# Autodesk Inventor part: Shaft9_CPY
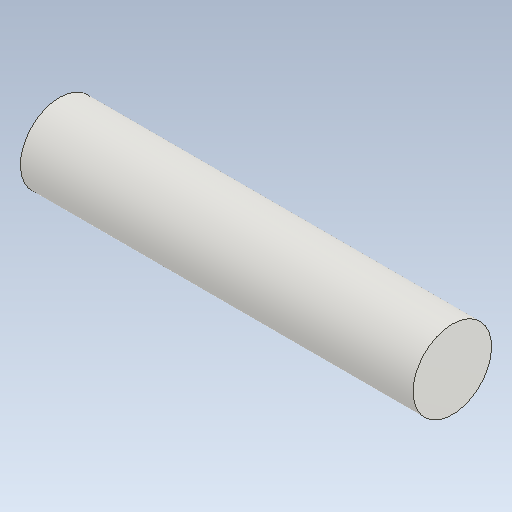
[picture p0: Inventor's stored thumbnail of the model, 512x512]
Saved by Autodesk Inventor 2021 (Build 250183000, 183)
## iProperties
Created: 2021-07
Part Number: Shaft9_CPY
Material: Steel
Document SubType Name: Modeling
Designer: CHIRAG
Density: 1 g/cm^3
Appearance: Plate
CustomPartVersion: 1
Author: CHIRAG
Length: 150.000 mm
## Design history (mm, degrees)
sketch "Main Sketch"
  geometry: L1 (0, 0)-(150, 0) reference; L2 (0, 0)-(0, 15); L3 (150, 15)-(150, 0); L4 (0, 15)-(150, 15)
  constraints: 8 end point, 3 horizontal, 2 vertical
  dimensions: "d3" = 30 diameter of L4 L1 (derived)
revolve "Revolution1" sketch "Main Sketch" stored, may be unused: angle "d4" = 0 deg
body "Solid1"
other parameters: "d0" = 0, "d1" = 0, "d2" = 0, "Length" = 150 [user parameter]
